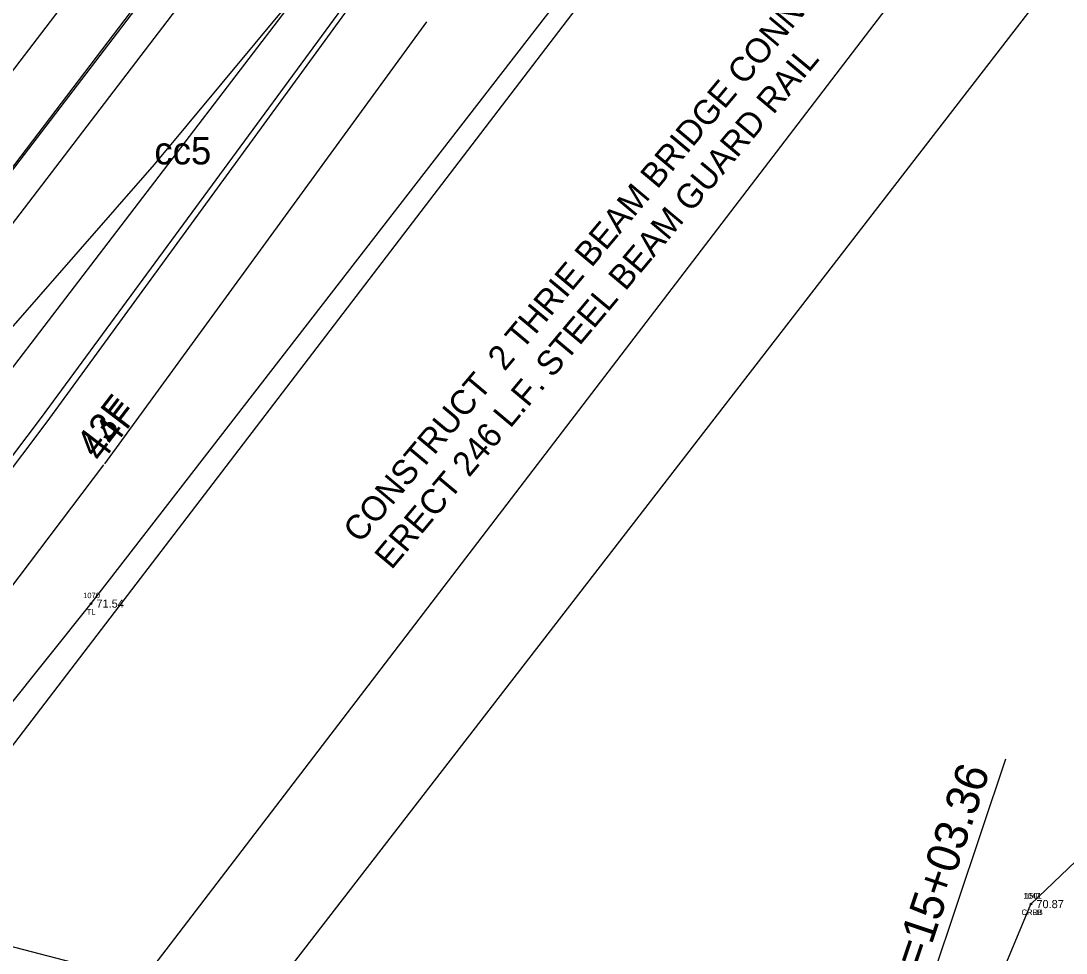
# Model space of a CAD drawing. Extents: x 2500794 to 2511032, y 910653 to 917533.
# Drawn here: x 2505953.3 to 2506144.5, y 913539.9 to 913710.5 of the extents above; entities that cross this region are included whole.
import ezdxf

# ---------------------------------------------------------------- set-up
doc = ezdxf.new("R2010")
doc.units = 0
for name, color, linetype in [('Default', 7, 'Continuous'), ('RD_EX_H2O_txCode', 7, 'Continuous'), ('RD_EX_H2O_WetLd', 7, 'Continuous'), ('RD_EX_Road', 7, 'Continuous'), ('RD_EX_RW', 7, 'Continuous'), ('RD_EX_TX_H2O_ELEV', 7, 'Continuous'), ('RD_EX_TX_VEG_ELEV', 7, 'Continuous'), ('RD_EX_VEG', 7, 'Continuous'), ('RD_EX_VEG_txCode', 7, 'Continuous'), ('RD_HC_Cl', 7, 'Continuous'), ('RD_HC_Data', 7, 'Continuous'), ('RD_PD_ALT1_TrvlWay', 7, 'Continuous'), ('RD_PD_CstnLmt', 7, 'Continuous'), ('RD_PD_CstnLmt_TX', 7, 'Continuous'), ('RD_PD_GR', 7, 'Continuous'), ('RD_PD_MedBWall', 7, 'Continuous'), ('RD_PD_RW', 7, 'Continuous'), ('RD_PD_Signals', 7, 'Continuous'), ('RD_Sketch9', 7, 'Continuous'), ('RD_SMD_Locator', 7, 'Continuous'), ('RD_XS_NPDES', 7, 'Continuous')]:
    doc.layers.add(name, color=color, linetype=linetype)

# ---------------------------------------------------------------- blocks, each defined once
blk = doc.blocks.new('POINT_DISPLAY')
at = {"layer": 'Default'}
blk.add_line((0, 0), (0, 0), dxfattribs=at)
blk = doc.blocks.new('Wetlands')
at = {"layer": 'Default'}
blk.add_lwpolyline([(636578.378, 232108.026), (636523.855, 232037.448), (636501.371, 232037.816), (636484.456, 232032.271), (636499.849, 232049.322), (636504.147, 232059.556), (636518.345, 232075.791), (636532.382, 232092.673), (636539.146, 232087.393), (636544.708, 232099.914), (636554.736, 232107.733), (636570.529, 232108.061), (636578.378, 232108.026)], dxfattribs=at)

msp = doc.modelspace()

# ---------------------------------------------------------------- linework, layer by layer
at = {"layer": 'RD_EX_H2O_txCode'}
for points in [[(2505644.45, 913807.58), (2505735.45, 913822.66), (2505800.85, 913818.32), (2505876.46, 913810.97), (2505914.87, 913815.81), (2505955.18, 913822.7), (2506003.2, 913816.23), (2506021.32, 913828.37), (2506028.84, 913826.12), (2506055.11, 913806.95), (2506104.38, 913808.33), (2506216.14, 913809.62), (2506311.29, 913789.92), (2506320.92, 913749.59), (2506242.37, 913648.56), (2506138.05, 913548.89)], [(2505762.26, 913658.11), (2505746.15, 913644.25), (2505726.47, 913615.21), (2505674.21, 913628.01), (2505666.25, 913620.58), (2505714.6, 913592.15), (2505793.9, 913560.45), (2505801.32, 913552.8), (2505803.7, 913539.77), (2505832.63, 913516.96), (2505848.42, 913517.19), (2505881.86, 913528.44), (2505910.2, 913538.78), (2505939.3, 913544.45), (2505946.25, 913542.54), (2505974.65, 913535.18), (2506004.11, 913524.7), (2506052.03, 913515.47), (2506115.49, 913494.68), (2506138.05, 913548.89)]]:
    msp.add_lwpolyline(points, dxfattribs=at)
at = {"layer": 'RD_EX_Road'}
msp.add_lwpolyline([(2506040.71, 913800.23), (2505979.73, 913720.47), (2505920.44, 913642.61), (2505859.42, 913562.61), (2505835.44, 913531.43), (2505833.77, 913527.25)], dxfattribs=at)
at = {"layer": 'RD_EX_RW'}
msp.add_line((2505900.77, 913580.27), (2506040.47, 913762.98), dxfattribs=at)
at = {"layer": 'RD_EX_VEG'}
msp.add_lwpolyline([(2506132.67, 913791.11), (2506063.24, 913729.37), (2505966.14, 913603.86), (2505918.37, 913544.18)], dxfattribs=at)
at = {"layer": 'RD_HC_Cl'}
msp.add_line((2505807.57, 913512.69), (2506748.89, 914743.92), dxfattribs=at)
at = {"layer": 'RD_HC_Data'}
msp.add_line((2506096.51, 913465.31), (2506133.46, 913575.48), dxfattribs=at)
at = {"layer": 'RD_PD_ALT1_TrvlWay'}
msp.add_line((2505854.3, 913555.7), (2506017.18, 913768.75), dxfattribs=at)
at = {"layer": 'RD_PD_CstnLmt'}
for p, q in [((2505958.15, 913637.1), (2506017.03, 913717.96)), ((2505897.77, 913557.38), (2505958.15, 913637.1))]:
    msp.add_line(p, q, dxfattribs=at)
at = {"layer": 'RD_PD_GR'}
msp.add_line((2505881.5, 913581.36), (2505999.52, 913735.81), dxfattribs=at)
at = {"layer": 'RD_PD_RW'}
msp.add_line((2505934.14, 913554.76), (2506073.83, 913737.47), dxfattribs=at)
at = {"layer": 'RD_PD_Signals'}
for p, q in [((2505957.08, 913637.92), (2506016.31, 913718.52)), ((2505896.79, 913558.14), (2505957.08, 913637.92))]:
    msp.add_line(p, q, dxfattribs=at)
at = {"layer": 'RD_Sketch9'}
msp.add_line((2505975.42, 913534.66), (2506308.52, 913970.35), dxfattribs=at)
at = {"layer": 'RD_SMD_Locator'}
for centre in [(2505966.14, 913603.86), (2506138.05, 913548.89), (2506138.05, 913548.89)]:
    msp.add_circle(centre, 0.15, dxfattribs=at)
at = {"layer": 'RD_XS_NPDES'}
for p, q in [((2505968.66, 913629.45), (2506027.54, 913710.31)), ((2505908.14, 913549.53), (2505968.51, 913629.25))]:
    msp.add_line(p, q, dxfattribs=at)

# ---------------------------------------------------------------- block references
at = {"layer": 'Default', "xscale": 3.937007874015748, "yscale": 3.937007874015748}
for name, p in [('Wetlands', (0, 0)), ('POINT_DISPLAY', (2505977.74, 913684.22)), ('POINT_DISPLAY', (2505977.74, 913684.22))]:
    msp.add_blockref(name, p, dxfattribs=at)
at = {"layer": 'RD_EX_H2O_WetLd', "xscale": 3.937007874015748, "yscale": 3.937007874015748}
msp.add_blockref('Wetlands', (0, 0), dxfattribs=at)

# ---------------------------------------------------------------- texts
at = {"layer": 'Default'}
msp.add_text('cc5', height=5, dxfattribs=at).set_placement((2505977.74, 913684.22))
msp.add_text('cc5', height=5, dxfattribs=at).set_placement((2505977.74, 913684.22))
at = {"layer": 'RD_EX_H2O_txCode'}
for s, p in [('1047', (2506136.66, 913549.89)), ('1501', (2506136.94, 913549.89)), ('CRRB', (2506136.32, 913546.89)), ('CRLB', (2506136.34, 913546.89))]:
    msp.add_text(s, height=1, dxfattribs=at).set_placement(p)
at = {"layer": 'RD_EX_TX_H2O_ELEV'}
msp.add_text('70.87', height=1.5, dxfattribs=at).set_placement((2506139.05, 913548.14))
msp.add_text('70.87', height=1.5, dxfattribs=at).set_placement((2506139.05, 913548.14))
at = {"layer": 'RD_EX_TX_VEG_ELEV'}
msp.add_text('71.54', height=1.5, dxfattribs=at).set_placement((2505967.14, 913603.11))
at = {"layer": 'RD_EX_VEG_txCode'}
for s, p in [('1070', (2505964.71, 913604.86)), ('TL', (2505965.37, 913601.86))]:
    msp.add_text(s, height=1, dxfattribs=at).set_placement(p)
at = {"layer": 'RD_HC_Data'}
msp.add_text('PI =15+03.36', height=6, rotation=71.46, dxfattribs=at).set_placement((2506115.28, 913527.58))
at = {"layer": 'RD_PD_CstnLmt_TX'}
msp.add_text('44F', height=5, rotation=52.6007, dxfattribs=at).set_placement((2505968.08, 913629.51))
at = {"layer": 'RD_PD_MedBWall'}
for s, p in [('CONSTRUCT  2 THRIE BEAM BRIDGE CONNECTOR', (2506015.36, 913614.73)), ('ERECT 246 L.F. STEEL BEAM GUARD RAIL', (2506021.1, 913609.91))]:
    msp.add_text(s, height=4.5, rotation=50.0195, dxfattribs=at).set_placement(p)
at = {"layer": 'RD_PD_Signals'}
msp.add_text('43F', height=5, rotation=52.6007, dxfattribs=at).set_placement((2505967.01, 913630.33))

doc.saveas('drawing.dxf')
